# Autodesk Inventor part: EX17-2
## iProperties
Shininess: 64.0
Length Units: 11272
Angle Units: 11279
Time Units: 11290
Mass Units: 11286
Length Display Precision: 3
Compacted: True
Part Number: EX17-2
Document SubType Name: Modeling
Created: 2002-11
Designer: E. MOSS
Project: EVERGREEN VALLEY COLLEGE
Description: SWIVEL
Authority: MS. TEACHER
Density: 0.0
Volumn: 0.0
Area: 0.0
PropertySet Name: Model Information
Control State: 0
Master: False
Checked Out: False
Author: E. MOSS
Revision Number: A
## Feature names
1. Extrusion1
2. Extrusion2
3. Hole1
4. Hole2
